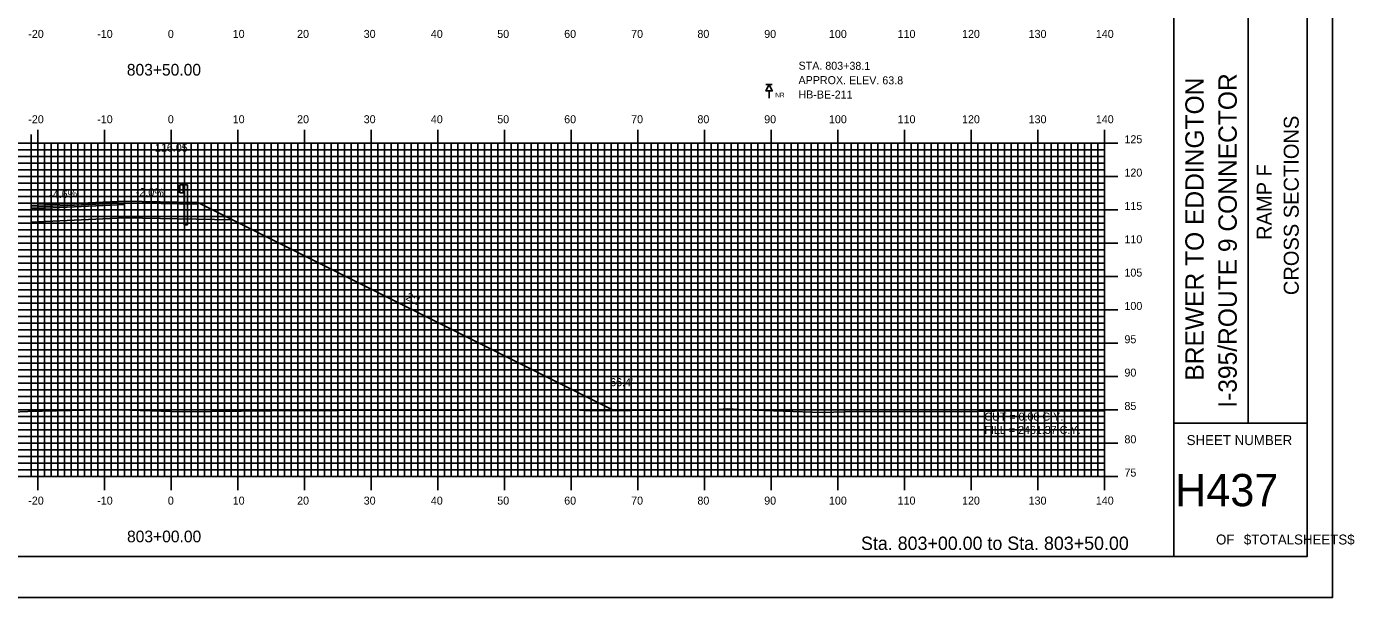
# Model space of a CAD drawing. Extents: x 92 to 435, y -1658 to -1438.
# Drawn here: x 236 to 435.1, y -1657.7 to -1572.1 of the extents above; entities that cross this region are included whole.
import ezdxf

# ---------------------------------------------------------------- set-up
doc = ezdxf.new("R2010")
doc.units = 0
for name, color, linetype in [('ANNOTATION', 7, 'Continuous'), ('BORDER', 7, 'Continuous'), ('BORING - NO REFUSAL', 7, 'Continuous'), ('D_Guardrail_Beam_Rt', 7, 'Continuous'), ('D_Roadway_Centerline_Text', 7, 'Continuous'), ('D_Roadway_Edge_Shoulder', 7, 'Continuous'), ('D_Roadway_Edge_TW', 7, 'Continuous'), ('D_Roadway_Pavement', 7, 'Continuous'), ('D_Roadway_SubGrade', 7, 'Continuous'), ('D_Text_Standard', 7, 'Continuous'), ('Default', 7, 'Continuous'), ('H_V ANNOTATION', 7, 'Continuous'), ('MAJOR', 7, 'Continuous'), ('MINOR', 7, 'Continuous'), ('PLOT BOUNDARY', 7, 'Continuous'), ('S_Roadway_Centerline', 7, 'Continuous')]:
    doc.layers.add(name, color=color, linetype=linetype)

msp = doc.modelspace()

# ---------------------------------------------------------------- linework, layer by layer
at = {"layer": 'BORDER'}
for p, q in [((408.02, -1651.6), (408.02, -1441.6)), ((419.2, -1631.6), (419.2, -1561.6)), ((408.02, -1631.6), (428.02, -1631.6))]:
    msp.add_line(p, q, dxfattribs=at)
msp.add_lwpolyline([(108.02, -1651.6), (428.02, -1651.6), (428.02, -1441.6), (108.02, -1441.6)], close=True, dxfattribs=at)
at = {"layer": 'BORING - NO REFUSAL'}
for p, q in [((347.8, -1580.8), (346.84, -1580.8)), ((347.32, -1581.76), (347.32, -1582.82))]:
    msp.add_line(p, q, dxfattribs=at)
msp.add_lwpolyline([(347.32, -1580.8), (347.8, -1581.76), (346.84, -1581.76)], close=True, dxfattribs=at)
at = {"layer": 'D_Guardrail_Beam_Rt'}
for p, q in [((258.83, -1595.96), (258.68, -1596.06)), ((258.68, -1596.2), (258.88, -1596.34)), ((258.88, -1596.54), (258.68, -1596.67)), ((258.68, -1596.82), (258.83, -1596.92)), ((258.92, -1595.94), (258.84, -1595.95)), ((258.84, -1596.92), (258.92, -1596.94)), ((258.91, -1596.4), (258.91, -1596.47)), ((258.92, -1595.86), (259.6, -1595.86)), ((258.92, -1597.02), (258.92, -1595.86)), ((259.6, -1597.02), (258.92, -1597.02)), ((259.44, -1595.86), (259.44, -1597.02)), ((259.54, -1595.86), (259.54, -1597.02)), ((259.58, -1601.86), (259.58, -1597.02)), ((259.6, -1595.86), (260.07, -1595.86)), ((259.6, -1595.86), (259.6, -1597.02)), ((260.07, -1595.86), (260.07, -1601.86)), ((259.58, -1601.86), (260.07, -1601.86))]:
    msp.add_line(p, q, dxfattribs=at)
for centre, major_axis, start_param, end_param in [((258.73, -1596.13), (-0.0877, 0), 5.323254, 7.243116), ((258.73, -1596.75), (-0.0877, 0), 5.323254, 7.243116), ((258.85, -1595.99), (-0.0417, 0), 4.907132, 5.323254), ((258.85, -1596.88), (-0.0417, 0), 0.959931, 1.376053), ((258.83, -1596.4), (0.0789, 0), 0, 0.959931), ((258.83, -1596.47), (0.0789, 0), 5.323254, 6.283185)]:
    msp.add_ellipse(centre, major_axis=major_axis, ratio=0.995501, start_param=start_param, end_param=end_param, dxfattribs=at)
at = {"layer": 'D_Roadway_Edge_Shoulder'}
msp.add_lwpolyline([(250.64, -1598.28), (258.64, -1598.44), (258.64, -1598.44), (261.64, -1598.5), (261.64, -1598.75), (250.64, -1598.53)], close=True, dxfattribs=at)
at = {"layer": 'D_Roadway_Edge_TW'}
msp.add_lwpolyline([(236.64, -1598.93), (250.64, -1598.28), (250.64, -1598.53), (236.64, -1599.18)], close=True, dxfattribs=at)
at = {"layer": 'D_Roadway_Pavement'}
msp.add_lwpolyline([(236.64, -1599.18), (250.64, -1598.53), (250.64, -1598.78), (236.64, -1599.43)], close=True, dxfattribs=at)
msp.add_lwpolyline([(250.64, -1598.53), (250.64, -1598.78)], dxfattribs=at)
msp.add_lwpolyline([(250.64, -1598.53), (250.64, -1598.78)], dxfattribs=at)
at = {"layer": 'D_Roadway_SubGrade'}
for p, q in [((236.64, -1588.29), (236.64, -1601.43)), ((266.85, -1601.1), (324.03, -1629.69))]:
    msp.add_line(p, q, dxfattribs=at)
for points in [[(236.64, -1599.43), (250.64, -1598.78), (250.64, -1600.78), (236.64, -1601.43)], [(250.64, -1598.78), (250.64, -1598.53), (261.64, -1598.75), (261.64, -1598.5), (266.85, -1601.1), (250.64, -1600.78)]]:
    msp.add_lwpolyline(points, close=True, dxfattribs=at)
at = {"layer": 'Default'}
msp.add_line((236.64, -1601.43), (236.64, -1591.61), dxfattribs=at)
at = {"layer": 'MAJOR'}
for p, q in [((237.62, -1587.6), (237.62, -1589.6)), ((247.62, -1587.6), (247.62, -1589.6)), ((257.62, -1587.6), (257.62, -1589.6)), ((267.62, -1587.6), (267.62, -1589.6)), ((277.62, -1587.6), (277.62, -1589.6)), ((287.62, -1587.6), (287.62, -1589.6)), ((297.62, -1587.6), (297.62, -1589.6)), ((307.62, -1587.6), (307.62, -1589.6)), ((317.62, -1587.6), (317.62, -1589.6)), ((327.62, -1587.6), (327.62, -1589.6)), ((337.62, -1587.6), (337.62, -1589.6)), ((347.62, -1587.6), (347.62, -1589.6)), ((357.62, -1587.6), (357.62, -1589.6)), ((367.62, -1587.6), (367.62, -1589.6)), ((377.62, -1587.6), (377.62, -1589.6)), ((387.62, -1587.6), (387.62, -1589.6)), ((397.62, -1587.6), (397.62, -1589.6)), ((117.62, -1589.6), (397.62, -1589.6)), ((117.62, -1589.6), (397.62, -1589.6)), ((237.62, -1639.6), (237.62, -1589.6)), ((247.62, -1639.6), (247.62, -1589.6)), ((257.62, -1639.6), (257.62, -1589.6)), ((267.62, -1639.6), (267.62, -1589.6)), ((277.62, -1639.6), (277.62, -1589.6)), ((287.62, -1639.6), (287.62, -1589.6)), ((297.62, -1639.6), (297.62, -1589.6)), ((307.62, -1639.6), (307.62, -1589.6)), ((317.62, -1639.6), (317.62, -1589.6)), ((327.62, -1639.6), (327.62, -1589.6)), ((337.62, -1639.6), (337.62, -1589.6)), ((347.62, -1639.6), (347.62, -1589.6)), ((357.62, -1639.6), (357.62, -1589.6)), ((367.62, -1639.6), (367.62, -1589.6)), ((377.62, -1639.6), (377.62, -1589.6)), ((387.62, -1639.6), (387.62, -1589.6)), ((399.63, -1589.6), (395.62, -1589.6)), ((397.62, -1639.6), (397.62, -1589.6)), ((397.62, -1639.6), (397.62, -1589.6)), ((117.62, -1594.6), (397.62, -1594.6)), ((399.63, -1594.6), (395.62, -1594.6)), ((117.62, -1599.6), (397.62, -1599.6)), ((399.63, -1599.6), (395.62, -1599.6)), ((117.62, -1604.6), (397.62, -1604.6)), ((399.63, -1604.6), (395.62, -1604.6)), ((117.62, -1609.6), (397.62, -1609.6)), ((399.63, -1609.6), (395.62, -1609.6)), ((117.62, -1614.6), (397.62, -1614.6)), ((399.63, -1614.6), (395.62, -1614.6)), ((117.62, -1619.6), (397.62, -1619.6)), ((399.63, -1619.6), (395.62, -1619.6)), ((117.62, -1624.6), (397.62, -1624.6)), ((399.63, -1624.6), (395.62, -1624.6)), ((117.62, -1629.6), (397.62, -1629.6)), ((399.63, -1629.6), (395.62, -1629.6)), ((117.62, -1634.6), (397.62, -1634.6)), ((399.63, -1634.6), (395.62, -1634.6)), ((117.62, -1639.6), (397.62, -1639.6)), ((117.62, -1639.6), (397.62, -1639.6)), ((237.62, -1641.61), (237.62, -1639.6)), ((247.62, -1641.61), (247.62, -1639.6)), ((257.62, -1641.61), (257.62, -1639.6)), ((267.62, -1641.61), (267.62, -1639.6)), ((277.62, -1641.61), (277.62, -1639.6)), ((287.62, -1641.61), (287.62, -1639.6)), ((297.62, -1641.61), (297.62, -1639.6)), ((307.62, -1641.61), (307.62, -1639.6)), ((317.62, -1641.61), (317.62, -1639.6)), ((327.62, -1641.61), (327.62, -1639.6)), ((337.62, -1641.61), (337.62, -1639.6)), ((347.62, -1641.61), (347.62, -1639.6)), ((357.62, -1641.61), (357.62, -1639.6)), ((367.62, -1641.61), (367.62, -1639.6)), ((377.62, -1641.61), (377.62, -1639.6)), ((387.62, -1641.61), (387.62, -1639.6)), ((399.63, -1639.6), (395.62, -1639.6)), ((397.62, -1641.61), (397.62, -1639.6))]:
    msp.add_line(p, q, dxfattribs=at)
at = {"layer": 'MINOR'}
for p, q in [((117.62, -1590.6), (397.62, -1590.6)), ((236.62, -1639.6), (236.62, -1589.6)), ((238.62, -1639.6), (238.62, -1589.6)), ((239.62, -1639.6), (239.62, -1589.6)), ((240.62, -1639.6), (240.62, -1589.6)), ((241.62, -1639.6), (241.62, -1589.6)), ((242.62, -1639.6), (242.62, -1589.6)), ((243.62, -1639.6), (243.62, -1589.6)), ((244.62, -1639.6), (244.62, -1589.6)), ((245.62, -1639.6), (245.62, -1589.6)), ((246.62, -1639.6), (246.62, -1589.6)), ((248.62, -1639.6), (248.62, -1589.6)), ((249.62, -1639.6), (249.62, -1589.6)), ((250.62, -1639.6), (250.62, -1589.6)), ((251.62, -1639.6), (251.62, -1589.6)), ((252.62, -1639.6), (252.62, -1589.6)), ((253.62, -1639.6), (253.62, -1589.6)), ((254.62, -1639.6), (254.62, -1589.6)), ((255.62, -1639.6), (255.62, -1589.6)), ((256.62, -1639.6), (256.62, -1589.6)), ((258.62, -1639.6), (258.62, -1589.6)), ((259.62, -1639.6), (259.62, -1589.6)), ((260.62, -1639.6), (260.62, -1589.6)), ((261.62, -1639.6), (261.62, -1589.6)), ((262.62, -1639.6), (262.62, -1589.6)), ((263.62, -1639.6), (263.62, -1589.6)), ((264.62, -1639.6), (264.62, -1589.6)), ((265.62, -1639.6), (265.62, -1589.6)), ((266.62, -1639.6), (266.62, -1589.6)), ((268.62, -1639.6), (268.62, -1589.6)), ((269.62, -1639.6), (269.62, -1589.6)), ((270.62, -1639.6), (270.62, -1589.6)), ((271.62, -1639.6), (271.62, -1589.6)), ((272.62, -1639.6), (272.62, -1589.6)), ((273.62, -1639.6), (273.62, -1589.6)), ((274.62, -1639.6), (274.62, -1589.6)), ((275.62, -1639.6), (275.62, -1589.6)), ((276.62, -1639.6), (276.62, -1589.6)), ((278.62, -1639.6), (278.62, -1589.6)), ((279.62, -1639.6), (279.62, -1589.6)), ((280.62, -1639.6), (280.62, -1589.6)), ((281.62, -1639.6), (281.62, -1589.6)), ((282.62, -1639.6), (282.62, -1589.6)), ((283.62, -1639.6), (283.62, -1589.6)), ((284.62, -1639.6), (284.62, -1589.6)), ((285.62, -1639.6), (285.62, -1589.6)), ((286.62, -1639.6), (286.62, -1589.6)), ((288.62, -1639.6), (288.62, -1589.6)), ((289.62, -1639.6), (289.62, -1589.6)), ((290.62, -1639.6), (290.62, -1589.6)), ((291.62, -1639.6), (291.62, -1589.6)), ((292.62, -1639.6), (292.62, -1589.6)), ((293.62, -1639.6), (293.62, -1589.6)), ((294.62, -1639.6), (294.62, -1589.6)), ((295.62, -1639.6), (295.62, -1589.6)), ((296.62, -1639.6), (296.62, -1589.6)), ((298.62, -1639.6), (298.62, -1589.6)), ((299.62, -1639.6), (299.62, -1589.6)), ((300.62, -1639.6), (300.62, -1589.6)), ((301.62, -1639.6), (301.62, -1589.6)), ((302.62, -1639.6), (302.62, -1589.6)), ((303.62, -1639.6), (303.62, -1589.6)), ((304.62, -1639.6), (304.62, -1589.6)), ((305.62, -1639.6), (305.62, -1589.6)), ((306.62, -1639.6), (306.62, -1589.6)), ((308.62, -1639.6), (308.62, -1589.6)), ((309.62, -1639.6), (309.62, -1589.6)), ((310.62, -1639.6), (310.62, -1589.6)), ((311.62, -1639.6), (311.62, -1589.6)), ((312.62, -1639.6), (312.62, -1589.6)), ((313.62, -1639.6), (313.62, -1589.6)), ((314.62, -1639.6), (314.62, -1589.6)), ((315.62, -1639.6), (315.62, -1589.6)), ((316.62, -1639.6), (316.62, -1589.6)), ((318.62, -1639.6), (318.62, -1589.6)), ((319.62, -1639.6), (319.62, -1589.6)), ((320.62, -1639.6), (320.62, -1589.6)), ((321.62, -1639.6), (321.62, -1589.6)), ((322.62, -1639.6), (322.62, -1589.6)), ((323.62, -1639.6), (323.62, -1589.6)), ((324.62, -1639.6), (324.62, -1589.6)), ((325.62, -1639.6), (325.62, -1589.6)), ((326.62, -1639.6), (326.62, -1589.6)), ((328.62, -1639.6), (328.62, -1589.6)), ((329.62, -1639.6), (329.62, -1589.6)), ((330.62, -1639.6), (330.62, -1589.6)), ((331.62, -1639.6), (331.62, -1589.6)), ((332.62, -1639.6), (332.62, -1589.6)), ((333.62, -1639.6), (333.62, -1589.6)), ((334.62, -1639.6), (334.62, -1589.6)), ((335.62, -1639.6), (335.62, -1589.6)), ((336.62, -1639.6), (336.62, -1589.6)), ((338.62, -1639.6), (338.62, -1589.6)), ((339.62, -1639.6), (339.62, -1589.6)), ((340.62, -1639.6), (340.62, -1589.6)), ((341.62, -1639.6), (341.62, -1589.6)), ((342.62, -1639.6), (342.62, -1589.6)), ((343.62, -1639.6), (343.62, -1589.6)), ((344.62, -1639.6), (344.62, -1589.6)), ((345.62, -1639.6), (345.62, -1589.6)), ((346.62, -1639.6), (346.62, -1589.6)), ((348.62, -1639.6), (348.62, -1589.6)), ((349.62, -1639.6), (349.62, -1589.6)), ((350.62, -1639.6), (350.62, -1589.6)), ((351.62, -1639.6), (351.62, -1589.6)), ((352.62, -1639.6), (352.62, -1589.6)), ((353.62, -1639.6), (353.62, -1589.6)), ((354.62, -1639.6), (354.62, -1589.6)), ((355.62, -1639.6), (355.62, -1589.6)), ((356.62, -1639.6), (356.62, -1589.6)), ((358.62, -1639.6), (358.62, -1589.6)), ((359.62, -1639.6), (359.62, -1589.6)), ((360.62, -1639.6), (360.62, -1589.6)), ((361.62, -1639.6), (361.62, -1589.6)), ((362.62, -1639.6), (362.62, -1589.6)), ((363.62, -1639.6), (363.62, -1589.6)), ((364.62, -1639.6), (364.62, -1589.6)), ((365.62, -1639.6), (365.62, -1589.6)), ((366.62, -1639.6), (366.62, -1589.6)), ((368.62, -1639.6), (368.62, -1589.6)), ((369.62, -1639.6), (369.62, -1589.6)), ((370.62, -1639.6), (370.62, -1589.6)), ((371.62, -1639.6), (371.62, -1589.6)), ((372.62, -1639.6), (372.62, -1589.6)), ((373.62, -1639.6), (373.62, -1589.6)), ((374.62, -1639.6), (374.62, -1589.6)), ((375.62, -1639.6), (375.62, -1589.6)), ((376.62, -1639.6), (376.62, -1589.6)), ((378.62, -1639.6), (378.62, -1589.6)), ((379.62, -1639.6), (379.62, -1589.6)), ((380.62, -1639.6), (380.62, -1589.6)), ((381.62, -1639.6), (381.62, -1589.6)), ((382.62, -1639.6), (382.62, -1589.6)), ((383.62, -1639.6), (383.62, -1589.6)), ((384.62, -1639.6), (384.62, -1589.6)), ((385.62, -1639.6), (385.62, -1589.6)), ((386.62, -1639.6), (386.62, -1589.6)), ((388.62, -1639.6), (388.62, -1589.6)), ((389.62, -1639.6), (389.62, -1589.6)), ((390.62, -1639.6), (390.62, -1589.6)), ((391.62, -1639.6), (391.62, -1589.6)), ((392.62, -1639.6), (392.62, -1589.6)), ((393.62, -1639.6), (393.62, -1589.6)), ((394.62, -1639.6), (394.62, -1589.6)), ((395.62, -1639.6), (395.62, -1589.6)), ((397.62, -1590.6), (395.62, -1590.6)), ((396.62, -1639.6), (396.62, -1589.6)), ((117.62, -1591.6), (397.62, -1591.6)), ((117.62, -1592.6), (397.62, -1592.6)), ((397.62, -1591.6), (395.62, -1591.6)), ((397.62, -1592.6), (395.62, -1592.6)), ((117.62, -1593.6), (397.62, -1593.6)), ((397.62, -1593.6), (395.62, -1593.6)), ((117.62, -1595.6), (397.62, -1595.6)), ((117.62, -1596.6), (397.62, -1596.6)), ((397.62, -1595.6), (395.62, -1595.6)), ((397.62, -1596.6), (395.62, -1596.6)), ((117.62, -1597.6), (397.62, -1597.6)), ((117.62, -1598.6), (397.62, -1598.6)), ((397.62, -1597.6), (395.62, -1597.6)), ((397.62, -1598.6), (395.62, -1598.6)), ((117.62, -1600.6), (397.62, -1600.6)), ((397.62, -1600.6), (395.62, -1600.6)), ((117.62, -1601.6), (397.62, -1601.6)), ((117.62, -1602.6), (397.62, -1602.6)), ((397.62, -1601.6), (395.62, -1601.6)), ((397.62, -1602.6), (395.62, -1602.6)), ((117.62, -1603.6), (397.62, -1603.6)), ((397.62, -1603.6), (395.62, -1603.6)), ((117.62, -1605.6), (397.62, -1605.6)), ((117.62, -1606.6), (397.62, -1606.6)), ((397.62, -1605.6), (395.62, -1605.6)), ((397.62, -1606.6), (395.62, -1606.6)), ((117.62, -1607.6), (397.62, -1607.6)), ((117.62, -1608.6), (397.62, -1608.6)), ((397.62, -1607.6), (395.62, -1607.6)), ((397.62, -1608.6), (395.62, -1608.6)), ((117.62, -1610.6), (397.62, -1610.6)), ((397.62, -1610.6), (395.62, -1610.6)), ((117.62, -1611.6), (397.62, -1611.6)), ((117.62, -1612.6), (397.62, -1612.6)), ((397.62, -1611.6), (395.62, -1611.6)), ((397.62, -1612.6), (395.62, -1612.6)), ((117.62, -1613.6), (397.62, -1613.6)), ((397.62, -1613.6), (395.62, -1613.6)), ((117.62, -1615.6), (397.62, -1615.6)), ((117.62, -1616.6), (397.62, -1616.6)), ((397.62, -1615.6), (395.62, -1615.6)), ((397.62, -1616.6), (395.62, -1616.6)), ((117.62, -1617.6), (397.62, -1617.6)), ((117.62, -1618.6), (397.62, -1618.6)), ((397.62, -1617.6), (395.62, -1617.6)), ((397.62, -1618.6), (395.62, -1618.6)), ((117.62, -1620.6), (397.62, -1620.6)), ((397.62, -1620.6), (395.62, -1620.6)), ((117.62, -1621.6), (397.62, -1621.6)), ((117.62, -1622.6), (397.62, -1622.6)), ((397.62, -1621.6), (395.62, -1621.6)), ((397.62, -1622.6), (395.62, -1622.6)), ((117.62, -1623.6), (397.62, -1623.6)), ((397.62, -1623.6), (395.62, -1623.6)), ((117.62, -1625.6), (397.62, -1625.6)), ((117.62, -1626.6), (397.62, -1626.6)), ((397.62, -1625.6), (395.62, -1625.6)), ((397.62, -1626.6), (395.62, -1626.6)), ((117.62, -1627.6), (397.62, -1627.6)), ((117.62, -1628.6), (397.62, -1628.6)), ((397.62, -1627.6), (395.62, -1627.6)), ((397.62, -1628.6), (395.62, -1628.6)), ((117.62, -1630.6), (397.62, -1630.6)), ((397.62, -1630.6), (395.62, -1630.6)), ((117.62, -1631.6), (397.62, -1631.6)), ((117.62, -1632.6), (397.62, -1632.6)), ((397.62, -1631.6), (395.62, -1631.6)), ((397.62, -1632.6), (395.62, -1632.6)), ((117.62, -1633.6), (397.62, -1633.6)), ((397.62, -1633.6), (395.62, -1633.6)), ((117.62, -1635.6), (397.62, -1635.6)), ((117.62, -1636.6), (397.62, -1636.6)), ((397.62, -1635.6), (395.62, -1635.6)), ((397.62, -1636.6), (395.62, -1636.6)), ((117.62, -1637.6), (397.62, -1637.6)), ((117.62, -1638.6), (397.62, -1638.6)), ((397.62, -1637.6), (395.62, -1637.6)), ((397.62, -1638.6), (395.62, -1638.6))]:
    msp.add_line(p, q, dxfattribs=at)
at = {"layer": 'PLOT BOUNDARY'}
msp.add_lwpolyline([(91.83, -1657.72), (431.83, -1657.72), (431.83, -1437.72), (91.83, -1437.72)], close=True, dxfattribs=at)
at = {"layer": 'S_Roadway_Centerline'}
msp.add_lwpolyline([(228.97, -1630.12), (236.13, -1629.82), (244.72, -1629.62), (248.39, -1629.54), (251.43, -1629.62), (259.27, -1629.87), (272.66, -1629.71), (293.1, -1629.64), (294.13, -1629.64), (295.07, -1629.66), (301.51, -1629.63), (318.16, -1629.56), (320.5, -1629.71), (338.97, -1629.6), (341.14, -1629.45), (343.6, -1629.59), (355.29, -1629.96), (360.44, -1629.81), (376.14, -1629.88), (381.13, -1629.8), (394.89, -1629.72), (397.62, -1629.71)], dxfattribs=at)

# ---------------------------------------------------------------- texts
at = {"layer": 'ANNOTATION'}
for s, rotation, p in [('-4.6%', 2.647, (239.37, -1597.91)), ('-2.0%', 358.8535, (252.33, -1597.51)), ('2:1', 333.4349, (292.74, -1613.01))]:
    msp.add_text(s, height=1.2, rotation=rotation, dxfattribs=at).set_placement(p)
at = {"layer": 'BORDER'}
for s, height, p in [('I-395/ROUTE 9 CONNECTOR', 2.7557, (417.47, -1629.27)), ('BREWER TO EDDINGTON', 2.7557, (412.51, -1625.2)), ('CROSS SECTIONS', 2.25, (426.76, -1612.38)), ('RAMP F', 2.25, (422.71, -1604.1))]:
    msp.add_text(s, height=height, rotation=90, dxfattribs=at).set_placement(p)
for s, height, p in [('SHEET NUMBER', 1.4905, (409.95, -1634.87)), ('H437', 4.839, (408.23, -1644.04)), ('OF', 1.491, (414.36, -1649.78)), ('$TOTALSHEETS$', 1.4905, (418.53, -1649.78))]:
    msp.add_text(s, height=height, dxfattribs=at).set_placement(p)
at = {"layer": 'BORING - NO REFUSAL'}
for s, p in [('STA. 803+38.1', (351.74, -1578.56)), ('APPROX. ELEV. 63.8', (351.73, -1580.72)), ('HB-BE-211', (351.72, -1582.88))]:
    msp.add_text(s, height=1.2, rotation=359.8142, dxfattribs=at).set_placement(p)
msp.add_text('NR', height=0.7, dxfattribs=at).set_placement((348.25, -1582.72))
at = {"layer": 'D_Roadway_Centerline_Text'}
msp.add_text('116.05', height=1.2, dxfattribs=at).set_placement((255.21, -1590.86))
at = {"layer": 'D_Text_Standard'}
for s, p in [("66.4'", (323.49, -1626.04)), ('CUT = 0.00 C.Y.', (379.62, -1631.2)), ('FILL = 2461.37 C.Y.', (379.62, -1633.2))]:
    msp.add_text(s, height=1.2, dxfattribs=at).set_placement(p)
at = {"layer": 'H_V ANNOTATION'}
for s, height, p in [('-20', 1.2, (236.21, -1573.8)), ('-10', 1.2, (246.55, -1573.8)), ('0', 1.2, (257.14, -1573.8)), ('10', 1.2, (266.87, -1573.8)), ('20', 1.2, (276.53, -1573.8)), ('30', 1.2, (286.52, -1573.8)), ('40', 1.2, (296.59, -1573.8)), ('50', 1.2, (306.55, -1573.8)), ('60', 1.2, (316.59, -1573.8)), ('70', 1.2, (326.63, -1573.8)), ('80', 1.2, (336.57, -1573.8)), ('90', 1.2, (346.59, -1573.8)), ('100', 1.2, (356.3, -1573.8)), ('110', 1.2, (366.6, -1573.8)), ('120', 1.2, (376.26, -1573.8)), ('130', 1.2, (386.25, -1573.8)), ('140', 1.2, (396.33, -1573.8)), ('803+50.00', 1.75, (250.99, -1579.45)), ('-20', 1.2, (236.21, -1586.6)), ('-10', 1.2, (246.55, -1586.6)), ('0', 1.2, (257.14, -1586.6)), ('10', 1.2, (266.87, -1586.6)), ('20', 1.2, (276.53, -1586.6)), ('30', 1.2, (286.52, -1586.6)), ('40', 1.2, (296.59, -1586.6)), ('50', 1.2, (306.55, -1586.6)), ('60', 1.2, (316.59, -1586.6)), ('70', 1.2, (326.63, -1586.6)), ('80', 1.2, (336.57, -1586.6)), ('90', 1.2, (346.59, -1586.6)), ('100', 1.2, (356.3, -1586.6)), ('110', 1.2, (366.6, -1586.6)), ('120', 1.2, (376.26, -1586.6)), ('130', 1.2, (386.25, -1586.6)), ('140', 1.2, (396.33, -1586.6)), ('125', 1.2, (400.62, -1589.6)), ('120', 1.2, (400.62, -1594.6)), ('115', 1.2, (400.62, -1599.6)), ('110', 1.2, (400.62, -1604.6)), ('105', 1.2, (400.62, -1609.6)), ('100', 1.2, (400.62, -1614.6)), ('95', 1.2, (400.62, -1619.6)), ('90', 1.2, (400.62, -1624.6)), ('85', 1.2, (400.62, -1629.6)), ('80', 1.2, (400.62, -1634.6)), ('75', 1.2, (400.62, -1639.6)), ('-20', 1.2, (236.21, -1643.8)), ('-10', 1.2, (246.55, -1643.8)), ('0', 1.2, (257.14, -1643.8)), ('10', 1.2, (266.87, -1643.8)), ('20', 1.2, (276.53, -1643.8)), ('30', 1.2, (286.52, -1643.8)), ('40', 1.2, (296.59, -1643.8)), ('50', 1.2, (306.55, -1643.8)), ('60', 1.2, (316.59, -1643.8)), ('70', 1.2, (326.63, -1643.8)), ('80', 1.2, (336.57, -1643.8)), ('90', 1.2, (346.59, -1643.8)), ('100', 1.2, (356.3, -1643.8)), ('110', 1.2, (366.6, -1643.8)), ('120', 1.2, (376.26, -1643.8)), ('130', 1.2, (386.25, -1643.8)), ('140', 1.2, (396.33, -1643.8)), ('803+00.00', 1.75, (251.02, -1649.45)), ('Sta. 803+00.00 to Sta. 803+50.00', 2.0004, (361.11, -1650.6))]:
    msp.add_text(s, height=height, dxfattribs=at).set_placement(p)

doc.saveas('drawing.dxf')
